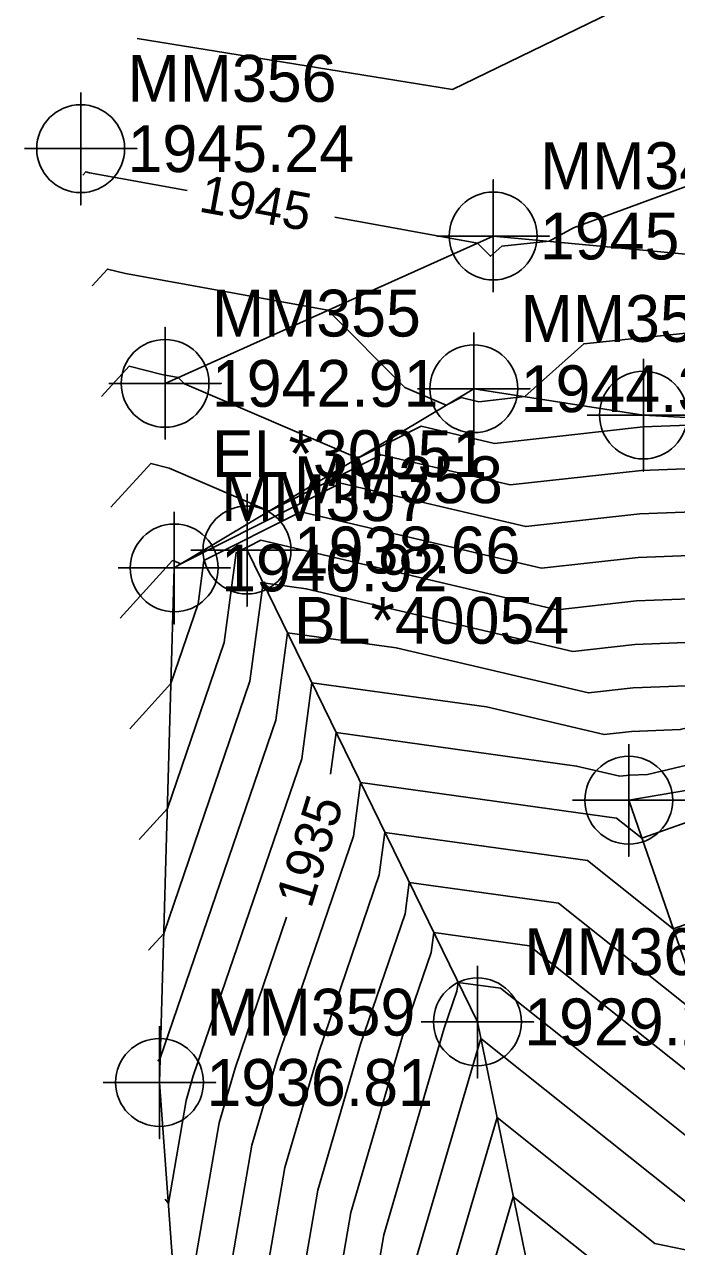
# Model space of a CAD drawing. Extents: x 1004378 to 1005103, y 553854 to 554288.
# Drawn here: x 1004886.9 to 1004921.7, y 553915.8 to 553981 of the extents above; entities that cross this region are included whole.
import ezdxf

# ---------------------------------------------------------------- set-up
doc = ezdxf.new("R2010")
doc.units = 0
for name, color, linetype in [('DTM Contours Major', 7, 'Continuous'), ('DTM Contours Major Text', 7, 'Continuous'), ('DTM Contours Minor', 7, 'Continuous'), ('Exist DTM Breakline', 7, 'Continuous'), ('Exist DTM Breakline Cogo Comment', 7, 'Continuous'), ('Exist DTM Breakline Cogo Elevation', 7, 'Continuous'), ('Exist DTM Breakline Cogo Number', 7, 'Continuous'), ('Exist DTM Breakline Cogo Point CELL', 7, 'Continuous'), ('Exist DTM Regular Point CELL', 7, 'Continuous'), ('Exist DTM Regular Point Cogo Elevation', 7, 'Continuous'), ('Exist DTM Regular Point Cogo Number', 7, 'Continuous'), ('Exist Roads Soil', 7, 'Continuous'), ('Exist Roads Soil Cogo Comment', 7, 'Continuous'), ('Exist Roads Soil Cogo Elevation', 7, 'Continuous'), ('Exist Roads Soil Cogo Number', 7, 'Continuous'), ('Exist Roads Soil Cogo Point CELL', 7, 'Continuous')]:
    doc.layers.add(name, color=color, linetype=linetype)

msp = doc.modelspace()

# ---------------------------------------------------------------- linework, layer by layer
at = {"layer": 'DTM Contours Major'}
for points in [[(1004947.118, 554041.088), (1004947.311, 554019.215), (1004947.454, 554017.827), (1004947.487, 554013.967), (1004946.931, 553996.538), (1004946.571, 553995.053), (1004931.009, 553978.241), (1004928.196, 553974.545), (1004916.189, 553970.124), (1004914.888, 553969.412), (1004912.358, 553969.149), (1004911.765, 553968.617), (1004911.067, 553969.318), (1004903.448, 553970.699)], [(1004962.31, 553997.555), (1004961.333, 553987.27), (1004959.141, 553973.696), (1004957.624, 553968.273), (1004957.585, 553968.134), (1004953.163, 553954.39), (1004946.098, 553947.597), (1004944.639, 553946.764), (1004920.141, 553940.962), (1004919.187, 553940.926), (1004918.652, 553940.867), (1004916.351, 553941.407), (1004903.524, 553943.188), (1004903.229, 553940.965)], [(1004895.576, 553972.125), (1004890.355, 553973.071), (1004890.169, 553973.119), (1004890.012, 553972.946)], [(1004944.754, 553959.487), (1004943.743, 553958.515), (1004937.467, 553954.931), (1004928.829, 553952.886), (1004919.63, 553952.541), (1004914.473, 553951.967), (1004901.641, 553954.979), (1004896.468, 553952.368), (1004896.162, 553950.066), (1004894.709, 553945.812), (1004892.507, 553943.392)], [(1004959.1, 553944.929), (1004959.013, 553944.368), (1004958.077, 553943.19), (1004951.417, 553933.392), (1004951.155, 553933.242), (1004929.405, 553920.793), (1004926.414, 553919.305), (1004924.709, 553919.658), (1004920.162, 553923.286), (1004912.286, 553929.547), (1004910.029, 553929.86), (1004909.966, 553929.387), (1004909.292, 553927.413), (1004906.06, 553916.388), (1004903.403, 553900.976), (1004901.694, 553893.379)], [(1004900.883, 553933.338), (1004898.134, 553925.288), (1004897.276, 553922.361), (1004895.153, 553910.049), (1004894.759, 553910.571)]]:
    msp.add_lwpolyline(points, dxfattribs=at)
at = {"layer": 'DTM Contours Minor'}
for points in [[(1004892.909, 553980.228), (1004909.736, 553977.519), (1004919.988, 553982.517), (1004925.173, 553984.426), (1004936.898, 553999.835), (1004937.254, 554000.219), (1004937.418, 554000.896), (1004939.715, 554013.407), (1004939.746, 554016.607), (1004940.982, 554023.681), (1004941.12, 554046.622), (1004942.146, 554051.575), (1004941.271, 554057.545), (1004943.194, 554079.367), (1004940.844, 554083.886), (1004927.509, 554103.798), (1004927.675, 554104.761), (1004926.297, 554106.983), (1004913.409, 554117.504), (1004910.609, 554119.787), (1004911.321, 554123.435)], [(1004948.41, 554048.498), (1004948.656, 554020.661), (1004949.129, 554016.073), (1004949.157, 554012.693), (1004948.622, 553995.909), (1004948.121, 553992.807), (1004944.939, 553981.431), (1004934.117, 553969.131), (1004932.752, 553967.238), (1004929.819, 553965.57), (1004924.739, 553964.771), (1004916.73, 553963.94), (1004913.587, 553961.121), (1004911.131, 553960.847), (1004910.199, 553961.066), (1004909.391, 553960.658), (1004907.185, 553961.606), (1004903.082, 553965.731), (1004892.29, 553967.686), (1004891.326, 553967.931), (1004890.511, 553967.035)], [(1004949.768, 554048.44), (1004950.001, 554022.107), (1004950.803, 554014.319), (1004950.827, 554011.419), (1004950.368, 553997.019), (1004949.345, 553990.683), (1004942.849, 553967.456), (1004941.373, 553965.778), (1004941.187, 553965.52), (1004932.749, 553960.721), (1004926.659, 553959.763), (1004919.896, 553959.51), (1004911.966, 553958.627), (1004908.059, 553959.544), (1004904.674, 553957.836), (1004895.429, 553961.81), (1004895.097, 553962.143), (1004894.225, 553962.301), (1004892.484, 553962.744), (1004891.01, 553961.125)], [(1004951.126, 554048.381), (1004951.345, 554023.554), (1004952.478, 554012.565), (1004952.498, 554010.145), (1004952.115, 553998.128), (1004950.57, 553988.56), (1004944.141, 553965.574), (1004943.976, 553964.983), (1004943.524, 553963.577), (1004942.801, 553962.882), (1004934.598, 553958.198), (1004932.304, 553957.655), (1004919.808, 553957.187), (1004912.802, 553956.407), (1004905.92, 553958.023), (1004899.957, 553955.013), (1004894.62, 553957.307), (1004893.641, 553957.556), (1004891.509, 553955.214)], [(1004952.484, 554048.322), (1004952.69, 554025), (1004954.152, 554010.811), (1004954.168, 554008.871), (1004953.861, 553999.237), (1004951.794, 553986.437), (1004946.067, 553965.959), (1004945.92, 553965.433), (1004944.901, 553962.265), (1004943.272, 553960.699), (1004936.032, 553956.565), (1004930.566, 553955.27), (1004919.719, 553954.864), (1004913.638, 553954.187), (1004903.78, 553956.501), (1004895.24, 553952.191), (1004894.867, 553952.351), (1004894.798, 553952.369), (1004892.008, 553949.303)], [(1004955.2, 554048.205), (1004955.379, 554027.893), (1004957.501, 554007.303), (1004957.509, 554006.323), (1004957.354, 554001.455), (1004954.243, 553982.19), (1004949.919, 553966.731), (1004949.808, 553966.333), (1004947.655, 553959.64), (1004944.214, 553956.331), (1004938.901, 553953.298), (1004927.091, 553950.501), (1004919.542, 553950.218), (1004915.309, 553949.747), (1004899.502, 553953.458), (1004898.18, 553952.79), (1004897.542, 553947.998), (1004894.519, 553939.143), (1004893.007, 553937.482)], [(1004956.558, 554048.146), (1004956.724, 554029.339), (1004959.176, 554005.549), (1004959.18, 554005.049), (1004959.101, 554002.565), (1004955.467, 553980.066), (1004951.846, 553967.116), (1004951.753, 553966.783), (1004949.032, 553958.328), (1004944.685, 553954.148), (1004940.335, 553951.664), (1004925.354, 553948.116), (1004919.453, 553947.895), (1004916.145, 553947.527), (1004901.925, 553950.865), (1004899.622, 553951.185), (1004898.923, 553945.93), (1004894.328, 553932.475), (1004893.506, 553931.571)], [(1004957.916, 554048.088), (1004958.069, 554030.785), (1004960.85, 554003.795), (1004960.85, 554003.775), (1004960.847, 554003.674), (1004956.692, 553977.943), (1004953.772, 553967.502), (1004953.697, 553967.233), (1004950.409, 553957.015), (1004945.156, 553951.964), (1004941.77, 553950.031), (1004923.616, 553945.732), (1004919.364, 553945.572), (1004916.98, 553945.307), (1004906.734, 553947.712), (1004900.923, 553948.519), (1004900.303, 553943.862), (1004894.138, 553925.806), (1004894.005, 553925.66)], [(1004971.881, 554041.705), (1004971.157, 554009.36), (1004970.735, 554000.573), (1004970.409, 553997.85), (1004967.896, 553971.406), (1004967.307, 553966.374), (1004963.018, 553949.502), (1004962.826, 553947.966), (1004960.054, 553930.094), (1004956.322, 553925.395), (1004955.382, 553924.012), (1004954.895, 553923.733), (1004952.275, 553922.234), (1004930.724, 553911.511), (1004918.442, 553914.051), (1004912.975, 553918.414), (1004911.33, 553912.804), (1004910.317, 553906.926), (1004906.034, 553887.884), (1004905.566, 553884.73), (1004904.694, 553883.365), (1004906.061, 553880.08)], [(1004966.137, 554039.463), (1004967.478, 554026.447), (1004967.045, 554007.095), (1004966.793, 554001.837), (1004966.598, 554000.209), (1004963.711, 553969.831), (1004963.525, 553968.246), (1004958.67, 553949.147), (1004958.67, 553949.145), (1004958.667, 553949.126), (1004958.663, 553949.121), (1004950.096, 553936.518), (1004949.909, 553936.411), (1004929.348, 553924.643), (1004924.856, 553923.056), (1004913.836, 553931.817), (1004908.728, 553932.526), (1004908.586, 553931.455), (1004907.061, 553926.988), (1004904.303, 553917.582), (1004901.098, 553898.992)], [(1004964.792, 554038.017), (1004966.378, 554022.632), (1004966.017, 554006.528), (1004965.807, 554002.153), (1004965.645, 554000.798), (1004962.665, 553969.437), (1004962.58, 553968.714), (1004960.36, 553959.981), (1004957.294, 553950.453), (1004953.909, 553947.198), (1004948.774, 553939.645), (1004948.663, 553939.581), (1004936.373, 553932.547), (1004923.184, 553927.887), (1004915.385, 553934.086), (1004907.427, 553935.191), (1004907.205, 553933.523), (1004904.829, 553926.563), (1004902.546, 553918.777), (1004898.793, 553897.009)], [(1004970.78, 554037.89), (1004970.129, 554008.794), (1004969.75, 554000.889), (1004969.456, 553998.44), (1004966.85, 553971.012), (1004966.362, 553966.842), (1004961.931, 553949.413), (1004961.787, 553948.261), (1004959.707, 553934.852), (1004956.907, 553931.326), (1004954.06, 553927.139), (1004953.648, 553926.903), (1004944.652, 553921.754), (1004929.287, 553914.109), (1004920.531, 553915.92), (1004912.107, 553922.642), (1004909.573, 553913.998), (1004908.012, 553904.943), (1004904.431, 553889.023), (1004903.852, 553885.125), (1004902.775, 553883.437), (1004903.84, 553880.88)], [(1004963.448, 554036.571), (1004965.277, 554018.817), (1004964.989, 554005.962), (1004964.822, 554002.47), (1004964.692, 554001.388), (1004961.753, 553970.463), (1004961.589, 553969.449), (1004961.476, 553969.044), (1004961.473, 553969.034), (1004955.917, 553951.766), (1004949.132, 553945.241), (1004947.453, 553942.771), (1004947.416, 553942.75), (1004943.398, 553940.451), (1004921.511, 553932.717), (1004916.934, 553936.356), (1004906.126, 553937.857), (1004905.825, 553935.591), (1004902.597, 553926.138), (1004900.789, 553919.972), (1004896.488, 553895.026)], [(1004962.103, 554035.124), (1004964.176, 554015.003), (1004963.961, 554005.396), (1004963.836, 554002.786), (1004963.739, 554001.977), (1004961.543, 553978.867), (1004960.365, 553971.573), (1004959.55, 553968.659), (1004959.529, 553968.584), (1004954.54, 553953.078), (1004946.569, 553945.413), (1004946.073, 553945.13), (1004931.594, 553941.701), (1004919.839, 553937.548), (1004918.483, 553938.626), (1004904.825, 553940.523), (1004904.444, 553937.659), (1004900.366, 553925.713), (1004899.032, 553921.166), (1004895.735, 553902.041), (1004895.123, 553902.853)], [(1004969.679, 554034.076), (1004969.101, 554008.227), (1004968.764, 554001.205), (1004968.504, 553999.029), (1004965.804, 553970.618), (1004965.416, 553967.31), (1004960.844, 553949.324), (1004960.748, 553948.556), (1004959.36, 553939.61), (1004957.492, 553937.258), (1004952.739, 553930.265), (1004952.402, 553930.072), (1004937.029, 553921.274), (1004927.851, 553916.707), (1004922.62, 553917.789), (1004911.24, 553926.87), (1004907.816, 553915.193), (1004905.707, 553902.959), (1004902.829, 553890.161), (1004902.139, 553885.52), (1004900.857, 553883.51), (1004901.619, 553881.68)], [(1004959.413, 554032.232), (1004961.975, 554007.374), (1004961.905, 554004.263), (1004961.865, 554003.418), (1004961.833, 554003.156), (1004961.122, 553995.674), (1004957.916, 553975.82), (1004955.698, 553967.888), (1004955.641, 553967.684), (1004951.786, 553955.703), (1004945.627, 553949.78), (1004943.204, 553948.397), (1004921.879, 553943.347), (1004919.275, 553943.249), (1004917.816, 553943.087), (1004911.542, 553944.56), (1004902.224, 553945.854), (1004901.684, 553941.794), (1004895.902, 553924.863), (1004895.519, 553923.556), (1004894.571, 553918.057), (1004894.395, 553918.29)]]:
    msp.add_lwpolyline(points, dxfattribs=at)
at = {"layer": 'Exist DTM Breakline'}
for points in [[(1004908.599, 554113.626), (1004928.542, 554104.358), (1004950.697, 554094.299), (1004945.541, 554080.331), (1004948.745, 554053.974), (1004946.395, 554048.586), (1004946.774, 554014.511), (1004946.946, 553994.845), (1004942.426, 553964.624), (1004933.56, 553959.38), (1004919.92, 553960.138), (1004910.869, 553961.543), (1004894.885, 553951.978), (1004894.101, 553924.52), (1004896.848, 553886.739), (1004896.026, 553883.694)], [(1004898.767, 553952.935), (1004911.06, 553927.75), (1004914.579, 553910.594), (1004912.831, 553883.055), (1004952.809, 553896.992)], [(1004946.811, 553944.29), (1004919.135, 553939.581), (1004925.719, 553920.561), (1004956.033, 553922.471)]]:
    msp.add_lwpolyline(points, dxfattribs=at)
at = {"layer": 'Exist DTM Breakline Cogo Point CELL'}
for points in [[(1004910.869, 553964.543), (1004910.869, 553958.543), (1004910.869, 553961.543), (1004913.869, 553961.543), (1004907.869, 553961.543)], [(1004919.92, 553963.138), (1004919.92, 553957.138), (1004919.92, 553960.138), (1004922.92, 553960.138), (1004916.92, 553960.138)], [(1004898.767, 553955.935), (1004898.767, 553949.935), (1004898.767, 553952.935), (1004901.767, 553952.935), (1004895.767, 553952.935)], [(1004894.885, 553954.978), (1004894.885, 553948.978), (1004894.885, 553951.978), (1004897.885, 553951.978), (1004891.885, 553951.978)], [(1004919.135, 553942.581), (1004919.135, 553936.581), (1004919.135, 553939.581), (1004922.135, 553939.581), (1004916.135, 553939.581)], [(1004911.06, 553930.75), (1004911.06, 553924.75), (1004911.06, 553927.75), (1004914.06, 553927.75), (1004908.06, 553927.75)], [(1004894.101, 553927.52), (1004894.101, 553921.52), (1004894.101, 553924.52), (1004897.101, 553924.52), (1004891.101, 553924.52)]]:
    msp.add_lwpolyline(points, dxfattribs=at)
for centre in [(1004910.869, 553961.543), (1004919.92, 553960.138), (1004898.767, 553952.935), (1004894.885, 553951.978), (1004919.135, 553939.581), (1004911.06, 553927.75), (1004894.101, 553924.52)]:
    msp.add_circle(centre, 2.344, dxfattribs=at)
at = {"layer": 'Exist DTM Regular Point CELL'}
msp.add_lwpolyline([(1004889.893, 553977.356), (1004889.893, 553971.356), (1004889.893, 553974.356), (1004892.893, 553974.356), (1004886.893, 553974.356)], dxfattribs=at)
msp.add_circle((1004889.893, 553974.356), 2.344, dxfattribs=at)
at = {"layer": 'Exist Roads Soil'}
msp.add_lwpolyline([(1004902.345, 554049.201), (1004911.013, 554044.44), (1004908.227, 554025.602), (1004914.669, 554009.493), (1004937.036, 554000.34), (1004928.257, 553968.154), (1004911.901, 553969.693), (1004894.395, 553961.828)], dxfattribs=at)
at = {"layer": 'Exist Roads Soil Cogo Point CELL'}
for points in [[(1004911.901, 553966.693), (1004911.901, 553972.693), (1004911.901, 553969.693), (1004914.901, 553969.693), (1004908.901, 553969.693)], [(1004894.395, 553958.828), (1004894.395, 553964.828), (1004894.395, 553961.828), (1004897.395, 553961.828), (1004891.395, 553961.828)]]:
    msp.add_lwpolyline(points, dxfattribs=at)
for centre in [(1004911.901, 553969.693), (1004894.395, 553961.828)]:
    msp.add_circle(centre, 2.344, dxfattribs=at)

# ---------------------------------------------------------------- texts
at = {"layer": 'DTM Contours Major Text'}
for s, rotation, p in [('1945', 349.72996, (1004896.134, 553971.008)), ('1935', 72.90107, (1004902.184, 553933.751))]:
    msp.add_text(s, height=2, rotation=rotation, dxfattribs=at).set_placement(p)
at = {"layer": 'Exist DTM Breakline Cogo Comment'}
msp.add_text('BL*40054', height=2.5, dxfattribs=at).set_placement((1004901.267, 553947.935))
at = {"layer": 'Exist DTM Breakline Cogo Elevation'}
for s, p in [('1944.31', (1004913.369, 553960.293)), ('1938.66', (1004901.267, 553951.685)), ('1940.92', (1004897.385, 553950.728)), ('1929.21', (1004913.56, 553926.5)), ('1936.81', (1004896.601, 553923.27))]:
    msp.add_text(s, height=2.5, dxfattribs=at).set_placement(p)
at = {"layer": 'Exist DTM Breakline Cogo Number'}
for s, p in [('MM354', (1004913.369, 553964.043)), ('MM358', (1004901.267, 553955.435)), ('MM357', (1004897.385, 553954.478)), ('MM363', (1004913.56, 553930.25)), ('MM359', (1004896.601, 553927.02))]:
    msp.add_text(s, height=2.5, dxfattribs=at).set_placement(p)
at = {"layer": 'Exist DTM Regular Point Cogo Elevation'}
msp.add_text('1945.24', height=2.5, dxfattribs=at).set_placement((1004892.393, 553973.106))
at = {"layer": 'Exist DTM Regular Point Cogo Number'}
msp.add_text('MM356', height=2.5, dxfattribs=at).set_placement((1004892.393, 553976.856))
at = {"layer": 'Exist Roads Soil Cogo Comment'}
msp.add_text('EL*30051', height=2.5, dxfattribs=at).set_placement((1004896.895, 553956.828))
at = {"layer": 'Exist Roads Soil Cogo Elevation'}
for s, p in [('1945.10', (1004914.401, 553968.443)), ('1942.91', (1004896.895, 553960.578))]:
    msp.add_text(s, height=2.5, dxfattribs=at).set_placement(p)
at = {"layer": 'Exist Roads Soil Cogo Number'}
for s, p in [('MM345', (1004914.401, 553972.193)), ('MM355', (1004896.895, 553964.328))]:
    msp.add_text(s, height=2.5, dxfattribs=at).set_placement(p)

doc.saveas('drawing.dxf')
